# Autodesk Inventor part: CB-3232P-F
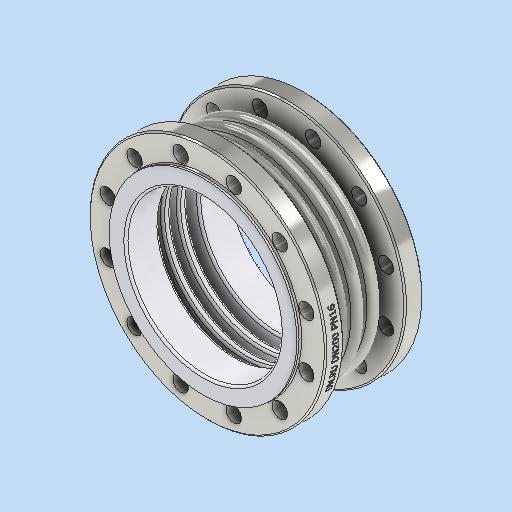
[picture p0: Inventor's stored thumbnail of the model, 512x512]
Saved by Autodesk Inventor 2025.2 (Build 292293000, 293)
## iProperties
Company: DN.RU
Created: 2026-04
Part Number: CB-3232P-F
Material: Типовые
Document SubType Name: Modeling
Designer: DN.RU
Density: 6.17872 g/cm^3
Appearance: По умолчанию
Description: D140-02144
Mass: 19600 g
Surface Area: 8147.13 cm^2
Volume: 3172.18 cm^3
Author: DN.RU
Title: Компенсатор сильфонный осевой DN.ru Ду200 Ру16
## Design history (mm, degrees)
sketch "Эскиз1"
  geometry: L1 (0, 0)-(0, -70); L2 (118.75, -70)-(118.75, 0); L3 (118.75, 0)-(0, 0); L4 (118.75, 0)-(118.75, 0); L5 (93.75, 0)-(143.75, 0); L6 (93.75, -7.5)-(143.75, -7.5); L7 (143.75, 7.5)-(93.75, 7.5); L8 (143.75, -5.5)-(93.75, -5.5); L9 (93.75, 5.5)-(143.75, 5.5); L10 (143.75, -15.5)-(93.75, -15.5); L11 (93.75, -17.5)-(143.75, -17.5); L12 (93.75, -23)-(143.75, -23); L13 (93.75, -30.5)-(143.75, -30.5); L14 (143.75, -28.5)-(93.75, -28.5); L15 (0, -70)-(118.75, -70); L16 (118.75, -70)-(110.75, -70); L17 (110.75, -70)-(110.75, -28.5); L18 (118.75, -17.5)-(116.75, -17.5); L19 (116.75, -17.5)-(116.75, -5.5); L20 (118.75, 5.5)-(116.75, 5.5); L21 (116.75, 5.5)-(116.75, 0); L22 (0, -70)-(0, -44); L23 (0, -44)-(170, -44); L24 (170, -44)-(170, -70); L25 (170, -70)-(0, -70); L26 (118.75, -44)-(118.75, -59); L27 (118.75, -59)-(122.75, -59); L28 (122.75, -59)-(122.75, -44); L29 (122.75, -44)-(118.75, -44); L30 (118.75, 0)-(151.25, 0); A1 r 7.5 centre (93.75, 0) between (93.75, 7.5) and (93.75, -7.5); A2 r 7.5 centre (143.75, 0) between (143.75, -7.5) and (143.75, 7.5); A3 r 5.5 centre (93.75, 0) between (93.75, 5.5) and (93.75, -5.5); A4 r 5.5 centre (143.75, 0) between (143.75, -5.5) and (143.75, 5.5); A5 r 5.5 centre (93.75, -23) between (93.75, -17.5) and (93.75, -28.5); A6 r 7.5 centre (93.75, -23) between (93.75, -15.5) and (93.75, -30.5); A7 r 5.5 centre (143.75, -23) between (143.75, -28.5) and (143.75, -17.5); A8 r 7.5 centre (143.75, -23) between (143.75, -30.5) and (143.75, -15.5); 20 further points
  constraints: 64 end point, 17 point on circle, 14 point on line, 8 centre point, 7 parallel, 5 perpendicular, 4 tangent, 3 midpoint, 2 vertical, 1 horizontal, 25 other
  dimensions: "d0" = 70 distance of L1.start L1.end; "d3" = 0 distance of L2.end L4.end; "d4" = 25 distance of L4.end L5.end; "d5" = 15 diameter of A2; "d6" = 2 distance between parallel lines of L6 L8; "d9" = 23 distance of L4.end point (118.75, -23); "d18" = 2 distance of L18.start L18.end; "d19" = 2 distance of L20.start L20.end; "d27" = 110.75 distance between parallel lines of L1 L17; "d28" = 8 distance between parallel lines of L2 L17; "d29" = 26 distance of L1.end L22.end; "d30" = 170 distance of L22.end L23.end; "d31" = 15 distance of L26.start L26.end; "d32" = 4 distance of L27.end L26.end
revolve "Вращение1" sketch "Эскиз1" stored, may be unused: angle "d20" = 360 deg
sketch "Эскиз3" dims "d33" = 295
  geometry: L1 (0, 0)-(74.331, 19.917); L2 (0, 0)-(76.954, 0); C1 r 11 at (142.474, 38.176); C2 r 11 at (104.298, 104.298); C3 r 11 at (38.176, 142.474); C4 r 11 at (-38.176, 142.474); C5 r 110.75 at (0, 0) reference; C6 r 132.5 at (0, 0); C7 r 170 at (0, 0) reference; C8 r 11 at (-104.298, 104.298); C9 r 11 at (-142.474, 38.176); C10 r 11 at (-142.474, -38.176); C11 r 11 at (-104.298, -104.298); C12 r 11 at (-38.176, -142.474); C13 r 11 at (38.176, -142.474); C14 r 11 at (104.298, -104.298); C15 r 11 at (142.474, -38.176); 1 further point
  constraints: 13 centre point, 4 end point, 2 coincident, 1 equal length, 1 horizontal, 1 point on line, 28 other
  dimensions: "d34" = 15 deg angle of L2 L1; "d35" = 22 diameter of C1; "d38" = 360 deg dimension on point (0, 0) C1.centre (derived); "d40" = 265 diameter of C6
  node "Эскиз — круговой массив1" dims "d38" = 360 deg (derived)
extrude "Выдавливание1" cut sketch "Эскиз3" stored distance "d41" = 10; taper "d42" = 0 deg
extrude "Выдавливание2" join sketch "Эскиз3" distance "d43" = 3; taper "d44" = 0 deg
chamfer "Фаска2" distance "d45" = 3; stored, may be unused: second distance "d46" = 2, angle "d47" = 45 deg
chamfer "Фаска3" distance "d48" = 2; stored, may be unused: second distance "d49" = 2, angle "d50" = 45 deg
mirror "Зеркальное отражение2"
fillet "Сопряжение2" dims "d51" = 3
node "РабПлоскость2"
sketch "Эскиз4"
  geometry: L1 (-60.476, 3.302)-(81.492, 3.302); L2 (81.492, 3.302)-(81.492, -37.818); L3 (81.492, -37.818)-(-60.476, -37.818); L4 (-60.476, -37.818)-(-60.476, 3.302); 1 further point
  constraints: 2 other
feature "Рельеф2" sketch "Эскиз4" dims "d3" = 0, "d52" = 0.1, "d53" = 0
sketch "Эскиз5"
  geometry: C1 r 110.75 at (0, 0) reference; C2 r 134.75 at (0, 0); 1 further point
  constraints: 1 centre point
  dimensions: "d54" = 24 radial gap between concentric circles of C1 C2
extrude "Выдавливание3" join sketch "Эскиз5" distance "d55" = 3; taper "d56" = 0 deg
fillet "Сопряжение3" dims "d57" = 3
mirror "Зеркальное отражение3"
feature "ɒ耀ɔ耀ɖ耀ɘ耀ɚ耀ɜ耀ɞ耀ɠ耀" dims "d0" = 70, "d3" = 0, "d4" = 25, "d5" = 15, "d6" = 2, "d7" = 20, "d9" = 23, "d10" = 10, "d12" = 10, "d18" = 2, "d19" = 2, "d20" = 360 deg, "d27" = 110.75, "d28" = 8, "d29" = 26, "d30" = 170, "d31" = 15, "d32" = 4, "d33" = 295, "d34" = 15 deg, "d35" = 22, "d36" = 120, "d38" = 360 deg (derived), "d40" = 265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
node "Твердое тело1"
node "Эскиз — прямоугольный массив1" dims "d9" = 23, "d12" = 10
